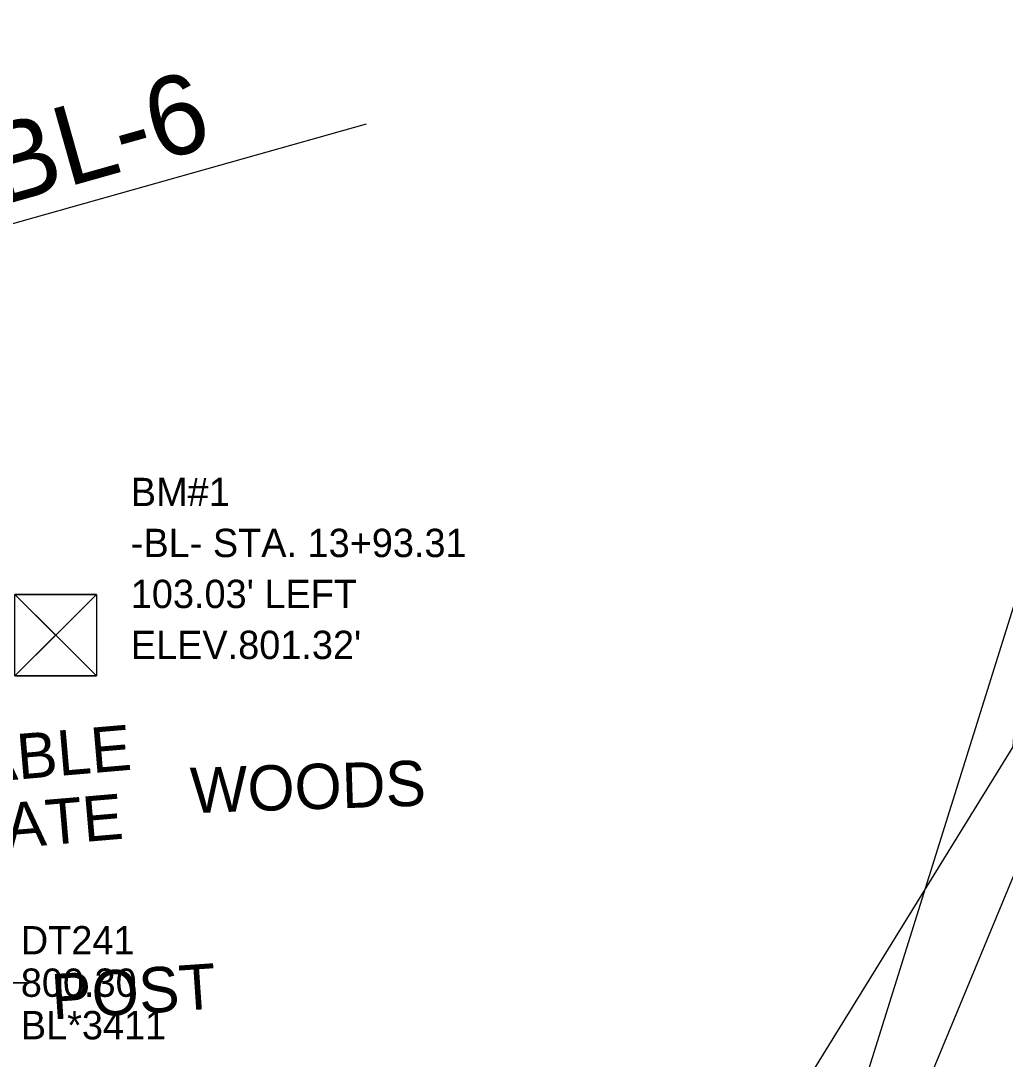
# Model space of a CAD drawing. Extents: x 1316460 to 1321645, y 684173 to 687077.
# Drawn here: x 1319546.4 to 1319633.3, y 686088.8 to 686180.5 of the extents above; entities that cross this region are included whole.
import ezdxf

# ---------------------------------------------------------------- set-up
doc = ezdxf.new("R2010")
doc.units = 0
for name, color, linetype in [('CTL Bench Mark CELL', 7, 'Continuous'), ('CTL Bench Mark Text', 7, 'Continuous'), ('Exist Horizontal Baseline Alignment Station Label', 7, 'Continuous'), ('Exist Hydrographic Water Edge Cogo Elevation', 7, 'Continuous'), ('Exist Other Culture Gate Cogo Comment', 7, 'Continuous'), ('Exist Other Culture Gate Cogo Elevation', 7, 'Continuous'), ('Exist Other Culture Gate Cogo Number', 7, 'Continuous'), ('Exist Other Culture Gate Cogo Point CELL', 7, 'Continuous'), ('Exist Other Culture Gate Text', 7, 'Continuous'), ('Exist Other Culture Located Object Text', 7, 'Continuous'), ('Exist Property Line', 7, 'Continuous'), ('Exist Vegetation Woods Line', 7, 'Continuous'), ('Exist Vegetation Woods Line Text', 7, 'Continuous')]:
    doc.layers.add(name, color=color, linetype=linetype)

# ---------------------------------------------------------------- blocks, each defined once
blk = doc.blocks.new('CTL BENCH MARK')
at = {"layer": 'CTL Bench Mark CELL'}
blk.add_line((0, 0), (0, 0), dxfattribs=at)
blk.add_lwpolyline([(-0.072, 0.07175), (0.07175, 0.07175), (0.07175, -0.072), (-0.072, -0.072)], close=True, dxfattribs=at)
for points in [[(0.07175, 0.07175), (-0.072, -0.072), (-0.000125, -0.000125), (0.07175, -0.072), (-0.072, 0.07175)], [(-0.000125, -0.000125), (0.07175, 0.07175), (-0.072, 0.07175), (-0.000125, -0.000125)], [(-0.000125, -0.000125), (-0.072, -0.072), (0.07175, -0.072), (-0.000125, -0.000125)]]:
    blk.add_lwpolyline(points, dxfattribs=at)

msp = doc.modelspace()

# ---------------------------------------------------------------- linework, layer by layer
at = {"layer": 'Exist Horizontal Baseline Alignment Station Label'}
msp.add_line((1319528.534, 686157.772), (1319576.949, 686171.412), dxfattribs=at)
at = {"layer": 'Exist Hydrographic Water Edge Cogo Elevation'}
msp.add_lwpolyline([(1319609.368, 686060.806), (1319617.664, 686076.398), (1319638.449, 686142.756), (1319653.036, 686186.565), (1319674.851, 686240.81)], dxfattribs=at)
at = {"layer": 'Exist Other Culture Gate Cogo Point CELL'}
msp.add_lwpolyline([(1319543.939, 686098.601), (1319543.939, 686092.601), (1319543.939, 686095.601), (1319546.939, 686095.601), (1319540.939, 686095.601)], dxfattribs=at)
at = {"layer": 'Exist Property Line'}
msp.add_line((1319623.434, 686079.333), (1319824.678, 686565.606), dxfattribs=at)
at = {"layer": 'Exist Vegetation Woods Line'}
msp.add_lwpolyline([(1319710.843, 686358.174), (1319684.477, 686276.047), (1319665.93, 686223.897), (1319652.823, 686201.99), (1319635.978, 686145.959), (1319634.019, 686116.412), (1319613.478, 686083.153), (1319563.005, 686080.164)], dxfattribs=at)

# ---------------------------------------------------------------- block references
at = {"layer": 'CTL Bench Mark CELL', "xscale": 50, "yscale": 50}
msp.add_blockref('CTL BENCH MARK', (1319549.521, 686126.289), dxfattribs=at)

# ---------------------------------------------------------------- texts
at = {"layer": 'CTL Bench Mark Text'}
for s, p in [('BM#1', (1319556.148, 686137.675)), ('-BL- STA. 13+93.31', (1319556.148, 686133.175)), ("103.03' LEFT", (1319556.148, 686128.675)), ("ELEV.801.32'", (1319556.148, 686124.175))]:
    msp.add_text(s, height=2.5, dxfattribs=at).set_placement(p)
at = {"layer": 'Exist Horizontal Baseline Alignment Station Label'}
msp.add_text('-BL-6', height=7, rotation=15.73495, dxfattribs=at).set_placement((1319541.529, 686163.302))
at = {"layer": 'Exist Other Culture Gate Cogo Comment'}
msp.add_text('BL*3411', height=2.5, dxfattribs=at).set_placement((1319546.439, 686090.601))
at = {"layer": 'Exist Other Culture Gate Cogo Elevation'}
msp.add_text('800.30', height=2.5, dxfattribs=at).set_placement((1319546.439, 686094.351))
at = {"layer": 'Exist Other Culture Gate Cogo Number'}
msp.add_text('DT241', height=2.5, dxfattribs=at).set_placement((1319546.439, 686098.101))
at = {"layer": 'Exist Other Culture Gate Text'}
for s, p in [('CABLE', (1319538.848, 686112.911)), ('GATE', (1319541.087, 686107.081))]:
    msp.add_text(s, height=4, rotation=4.89911, dxfattribs=at).set_placement(p)
at = {"layer": 'Exist Other Culture Located Object Text'}
msp.add_text('POST', height=4, rotation=3.87854, dxfattribs=at).set_placement((1319549.27, 686092.35))
at = {"layer": 'Exist Vegetation Woods Line Text'}
msp.add_text('WOODS', height=4, rotation=1.84763, dxfattribs=at).set_placement((1319561.461, 686110.571))

doc.saveas('drawing.dxf')
